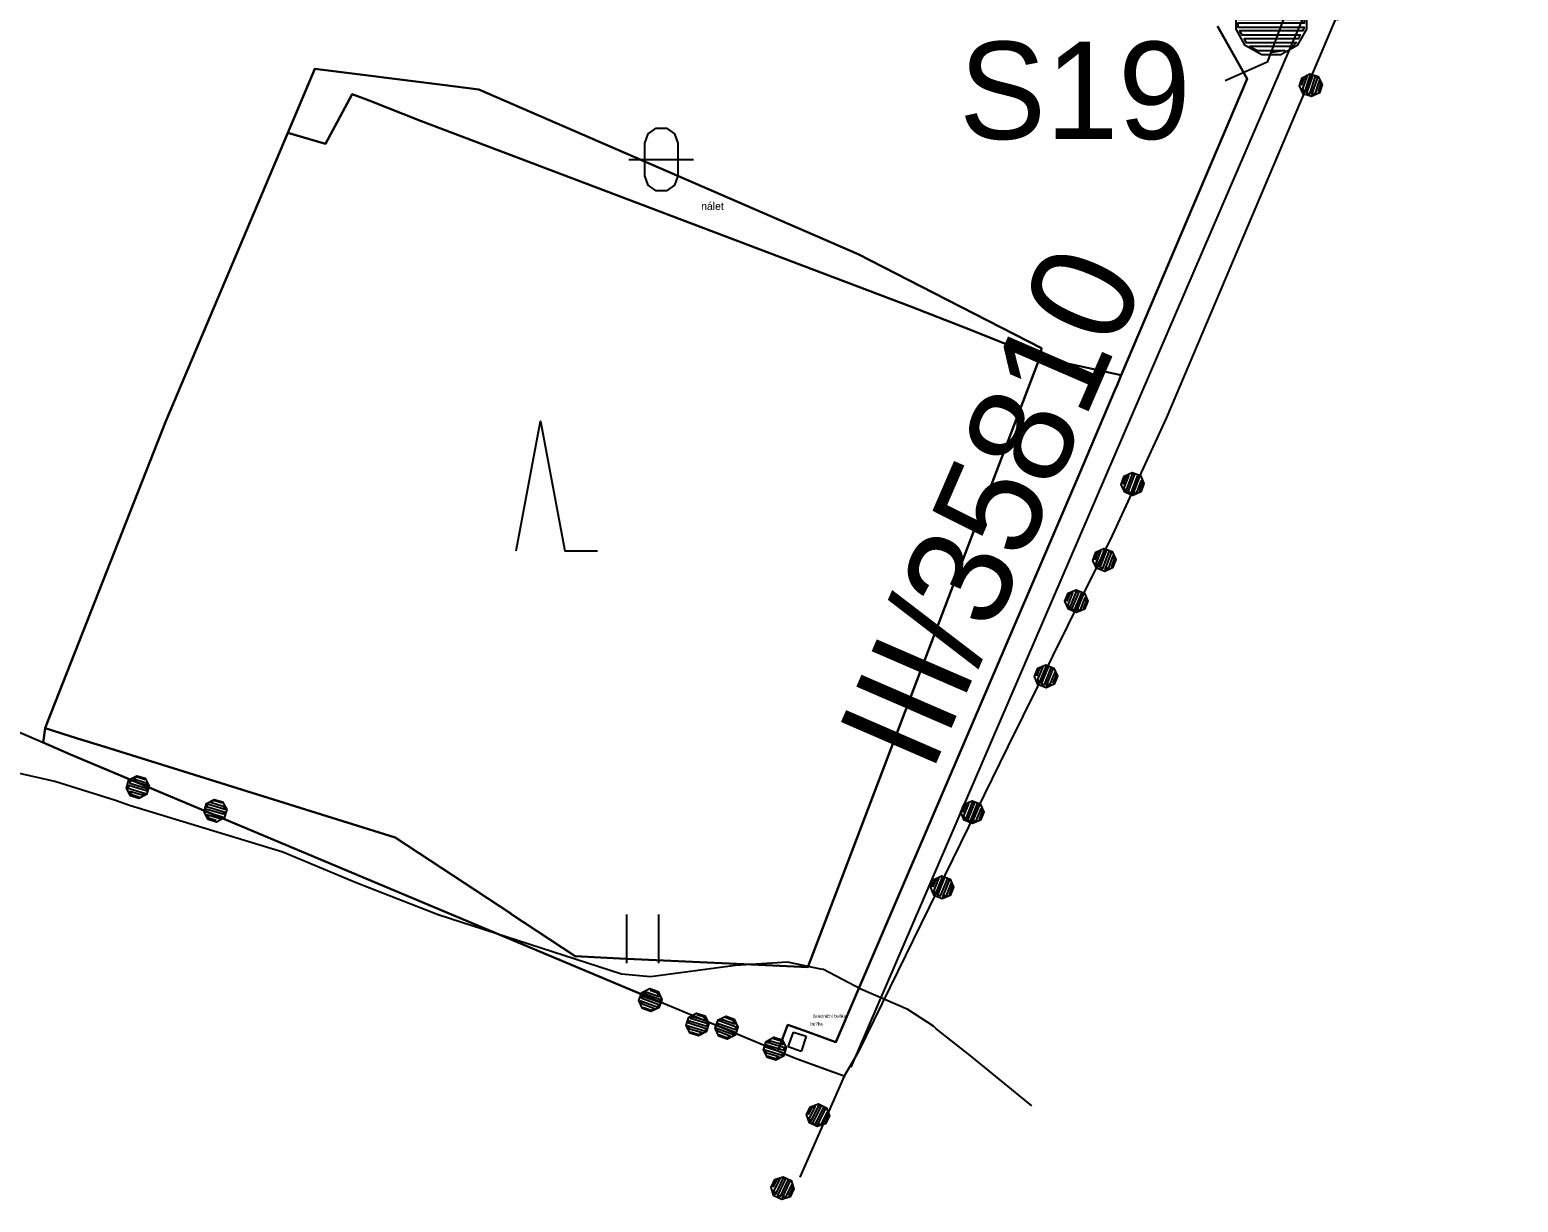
# Model space of a CAD drawing. Extents: x -645676 to -642474, y -1077513 to -1072613.
# Drawn here: x -642883 to -642653.5, y -1075517.7 to -1075337 of the extents above; entities that cross this region are included whole.
import ezdxf

# ---------------------------------------------------------------- set-up
doc = ezdxf.new("R2010")
doc.units = 0
for name, color, linetype in [('_elezni_n__tra_', 7, 'Continuous'), ('DOPRAVA', 7, 'Continuous'), ('DOPRAVA_MIMO_OBV', 7, 'Continuous'), ('Krajinn__zele____popis___stav', 7, 'Continuous'), ('KULTURY_STAV', 7, 'Continuous'), ('KULTURY_ZNACKY', 7, 'Continuous'), ('OBVOD_PU', 7, 'Continuous'), ('PC_OBJ_POPIS_NAVRH', 7, 'Continuous'), ('PC_OBJEKTY_NAVRH', 7, 'Continuous'), ('PC_STAN_NAVRH', 7, 'Continuous'), ('SDELOVACI', 7, 'Continuous'), ('SPRAV_HR_STAV', 7, 'Continuous')]:
    doc.layers.add(name, color=color, linetype=linetype)

# ---------------------------------------------------------------- blocks, each defined once
blk = doc.blocks.new('$406')
blk.add_lwpolyline([(-0.19, 0.72), (0.2, 0.72), (0.54, 0.53), (0.73, 0.19), (0.73, -0.2), (0.54, -0.54), (0.2, -0.73), (-0.19, -0.73), (-0.53, -0.54), (-0.72, -0.2), (-0.72, 0.19), (-0.53, 0.53), (-0.2, 0.72), (-0.28, 0.64), (0.28, 0.64), (0.44, 0.56), (-0.44, 0.56), (-0.52, 0.48), (0.52, 0.48), (0.56, 0.4), (-0.55, 0.4), (-0.6, 0.32), (0.6, 0.32), (0.68, 0.24), (-0.59, 0.24), (-0.65, 0.24), (-0.68, 0.16), (0.59, 0.16), (0.68, 0.16), (0.68, 0.08), (-0.59, 0.08), (-0.68, 0.08), (-0.68, 0), (0.59, 0), (0.68, 0), (0.68, -0.08), (-0.59, -0.08), (-0.68, -0.08), (-0.68, -0.16), (0.59, -0.16), (0.68, -0.16), (0.65, -0.24), (-0.62, -0.24), (-0.65, -0.24), (-0.6, -0.32), (0.6, -0.32), (0.56, -0.4), (-0.55, -0.4), (-0.52, -0.48), (0.52, -0.48), (0.44, -0.56), (-0.44, -0.56), (-0.28, -0.64), (0.28, -0.64), (-0.02, -0.69)])
blk = doc.blocks.new('3$0800')
blk.add_lwpolyline([(-0.75, 0), (0, 4), (0.75, 0), (1.75, 0)])
blk = doc.blocks.new('3$0600')
for p, q in [((-0.5, 1.5), (-0.5, 0)), ((0.5, 0), (0.5, 1.5))]:
    blk.add_line(p, q)
blk = doc.blocks.new('3$1600')
for points in [[(-0.5, 1.5), (-0.4, 1.79), (-0.15, 1.97), (0.16, 1.97), (0.41, 1.79), (0.51, 1.5), (0.51, 0.5), (0.41, 0.21), (0.16, 0.03), (-0.15, 0.03), (-0.4, 0.21), (-0.5, 0.5), (-0.5, 1.5)], [(-1, 1), (0.27, 1), (1, 1)]]:
    blk.add_lwpolyline(points)
blk = doc.blocks.new('$935')
blk.add_lwpolyline([(-2, -1), (-1, 0), (1, 0), (2, -1)])
blk = doc.blocks.new('2$0620')
for points in [[(-1.07, 0.32), (-0.88, 0.13), (-0.88, -0.14), (-1.07, -0.33), (-1.34, -0.33), (-1.53, -0.14), (-1.53, 0.13), (-1.34, 0.32), (-1.07, 0.32), (-1.08, 0.28), (-1.32, 0.28), (-1.4, 0.2), (-1, 0.2), (-0.92, 0.12), (-1.48, 0.12), (-1.48, 0.04), (-0.92, 0.04), (-0.92, -0.04), (-1.48, -0.04), (-1.48, -0.12), (-0.92, -0.12), (-1, -0.2), (-1.4, -0.2), (-1.32, -0.28), (-1.08, -0.28)], [(1.43, 0.32), (1.62, 0.13), (1.62, -0.14), (1.43, -0.33), (1.16, -0.33), (0.97, -0.14), (0.97, 0.13), (1.16, 0.32), (1.43, 0.32), (1.4, 0.28), (1.16, 0.28), (1.08, 0.2), (1.48, 0.2), (1.56, 0.12), (1, 0.12), (1, 0.04), (1.56, 0.04), (1.56, -0.04), (1, -0.04), (1, -0.12), (1.56, -0.12), (1.48, -0.2), (1.08, -0.2), (1.16, -0.28), (1.4, -0.28)]]:
    blk.add_lwpolyline(points)

msp = doc.modelspace()

# ---------------------------------------------------------------- linework, layer by layer
at = {"layer": '_elezni_n__tra_'}
for p, q in [((-642766.03, -1075493.8), (-642765.19, -1075491.51)), ((-642765.19, -1075491.51), (-642763.27, -1075492.16)), ((-642764, -1075494.5), (-642766.03, -1075493.8)), ((-642763.27, -1075492.16), (-642764, -1075494.5))]:
    msp.add_line(p, q, dxfattribs=at)
at = {"layer": 'DOPRAVA'}
msp.add_lwpolyline([(-642653.47, -1075258.11), (-642756.35, -1075496.91)], dxfattribs=at)
at = {"layer": 'DOPRAVA_MIMO_OBV'}
msp.add_lwpolyline([(-642757.41, -1075498.33), (-642764.25, -1075513.87)], dxfattribs=at)
at = {"layer": 'KULTURY_STAV'}
for points in [[(-642676.53, -1075323.31), (-642707.69, -1075396.77), (-642716.07, -1075414.98), (-642732.16, -1075447.5), (-642755.26, -1075494.63), (-642757.41, -1075498.33), (-642760.44, -1075497.22), (-642765.04, -1075495.53), (-642767.62, -1075494.46), (-642766.21, -1075490.73), (-642766.08, -1075490.39), (-642762.89, -1075491.54), (-642758.67, -1075493.07), (-642755.01, -1075484.54), (-642721.18, -1075405.56), (-642715.6, -1075392.43), (-642715.3, -1075391.8), (-642715.33, -1075391.79), (-642714.67, -1075390.24), (-642695.24, -1075344.57), (-642699.86, -1075336.44)], [(-642699.86, -1075336.44), (-642695.24, -1075344.57), (-642714.67, -1075390.24), (-642726.24, -1075387.74), (-642727.22, -1075387.53), (-642727.19, -1075387.39), (-642726.95, -1075386.07), (-642745.63, -1075376.53), (-642755.25, -1075371.61), (-642813.72, -1075346.23), (-642819.34, -1075345.51), (-642838.99, -1075343), (-642843.16, -1075352.87), (-642861.96, -1075397.33), (-642880.26, -1075443.82), (-642880.6, -1075444.68), (-642880.91, -1075446.88), (-642876.66, -1075448.7), (-642931.51, -1075425.22), (-642982.25, -1075403.81), (-643000.98, -1075395.62), (-643034.07, -1075381.69), (-643051.73, -1075373.59), (-643088.33, -1075357.65)], [(-642838.99, -1075343), (-642819.34, -1075345.51), (-642813.72, -1075346.23), (-642755.25, -1075371.61), (-642745.63, -1075376.53), (-642726.95, -1075386.07), (-642727.19, -1075387.39), (-642727.86, -1075387.14), (-642727.91, -1075387.26), (-642738.82, -1075382.9), (-642747.04, -1075379.73), (-642822.71, -1075351.06), (-642830.63, -1075347.92), (-642833.27, -1075346.93), (-642837.34, -1075354.58), (-642843.16, -1075352.87), (-642838.99, -1075343)], [(-642833.27, -1075346.93), (-642830.63, -1075347.92), (-642822.71, -1075351.06), (-642747.04, -1075379.73), (-642738.82, -1075382.9), (-642727.91, -1075387.26), (-642727.86, -1075387.14), (-642727.19, -1075387.39), (-642727.22, -1075387.53), (-642762.98, -1075481.52), (-642769.49, -1075481.21), (-642792.01, -1075480.15), (-642792.02, -1075480.15), (-642798.85, -1075479.83), (-642808.79, -1075473.26), (-642808.8, -1075473.25), (-642826.6, -1075461.5), (-642871.36, -1075447.55), (-642875.61, -1075446.23), (-642880.6, -1075444.68), (-642880.26, -1075443.82), (-642861.96, -1075397.33), (-642843.16, -1075352.87), (-642837.34, -1075354.58), (-642833.27, -1075346.93)], [(-642727.22, -1075387.53), (-642726.24, -1075387.74), (-642714.67, -1075390.24), (-642715.33, -1075391.79), (-642715.3, -1075391.8), (-642715.6, -1075392.43), (-642721.18, -1075405.56), (-642755.01, -1075484.54), (-642758.67, -1075493.07), (-642762.89, -1075491.54), (-642766.08, -1075490.39), (-642766.21, -1075490.73), (-642767.62, -1075494.46), (-642785.89, -1075486.85), (-642876.66, -1075448.7), (-642880.91, -1075446.88), (-642880.6, -1075444.68), (-642875.61, -1075446.23), (-642871.36, -1075447.55), (-642826.6, -1075461.5), (-642808.8, -1075473.25), (-642808.79, -1075473.26), (-642798.85, -1075479.83), (-642792.02, -1075480.15), (-642792.01, -1075480.15), (-642769.49, -1075481.21), (-642762.98, -1075481.52), (-642727.22, -1075387.53)]]:
    msp.add_lwpolyline(points, dxfattribs=at)
at = {"layer": 'OBVOD_PU'}
msp.add_lwpolyline([(-642676.53, -1075323.31), (-642707.69, -1075396.77), (-642716.07, -1075414.98), (-642732.16, -1075447.5), (-642755.26, -1075494.63), (-642757.41, -1075498.33), (-642765.04, -1075495.53), (-642785.89, -1075486.85), (-642876.66, -1075448.7), (-642931.51, -1075425.22), (-642982.25, -1075403.81), (-643000.98, -1075395.62), (-643034.07, -1075381.69), (-643051.73, -1075373.59), (-643088.33, -1075357.65)], dxfattribs=at)
at = {"layer": 'SDELOVACI'}
msp.add_lwpolyline([(-642728.48, -1075502.86), (-642737.73, -1075495.35), (-642743.24, -1075490.96), (-642743.61, -1075490.6), (-642747.58, -1075488.02), (-642754.81, -1075484.9), (-642760.56, -1075481.89), (-642760.99, -1075481.81), (-642766.13, -1075480.74), (-642774.14, -1075481.26), (-642787.27, -1075482.99), (-642791.75, -1075482.57), (-642819.97, -1075473.46), (-642832.61, -1075468.53), (-642843.93, -1075463.77), (-642867.57, -1075456.57), (-642869.75, -1075455.83), (-642879.11, -1075452.9), (-642899.76, -1075448.19)], dxfattribs=at)
at = {"layer": 'SPRAV_HR_STAV'}
for p, q in [((-642676.53, -1075323.31), (-642707.69, -1075396.77)), ((-642707.69, -1075396.77), (-642716.07, -1075414.98)), ((-642716.07, -1075414.98), (-642732.16, -1075447.5)), ((-642876.66, -1075448.7), (-642931.51, -1075425.22)), ((-642732.16, -1075447.5), (-642755.26, -1075494.63)), ((-642876.66, -1075448.7), (-642785.89, -1075486.85)), ((-642765.04, -1075495.53), (-642785.89, -1075486.85)), ((-642757.41, -1075498.33), (-642765.04, -1075495.53)), ((-642755.26, -1075494.63), (-642757.41, -1075498.33))]:
    msp.add_line(p, q, dxfattribs=at)

# ---------------------------------------------------------------- block references
at = {"layer": 'KULTURY_ZNACKY', "xscale": 5, "yscale": 5}
for name, p in [('3$1600', (-642785.61, -1075362)), ('3$0800', (-642804.2, -1075417.34)), ('3$0600', (-642788.47, -1075480.87))]:
    msp.add_blockref(name, p, dxfattribs=at)
at = {"layer": 'PC_OBJEKTY_NAVRH', "xscale": 5, "yscale": 5, "rotation": -110.90214800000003}
msp.add_blockref('$935', (-642690.42, -1075337.32), dxfattribs=at)
at = {"layer": 'PC_STAN_NAVRH', "xscale": 7.5, "yscale": 7.5}
msp.add_blockref('$406', (-642691.58, -1075335.38), dxfattribs=at)
at = {"layer": 'SPRAV_HR_STAV'}
for p, xscale, yscale, rotation in [((-642683.36, -1075339.42), 5, 5, -108.674282), ((-642715.01, -1075412.67), 5.000000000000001, 5.000000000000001, -110.43017300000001), ((-642723.83, -1075430.67), 5, 5, -112.07201000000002), ((-642860.53, -1075455.48), 4.999999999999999, 5.000000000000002, -16.911367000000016), ((-642739.86, -1075463.21), 5, 5, -111.85435500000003), ((-642781.2, -1075488.8), 5, 5, 160.144801), ((-642773.84, -1075492.3), 5, 5, 162.638134), ((-642764.05, -1075509.76), 4.999999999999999, 5, -115.97406899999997)]:
    msp.add_blockref('2$0620', p, dxfattribs=dict(at, xscale=xscale, yscale=yscale, rotation=rotation))

# ---------------------------------------------------------------- texts
at = {"layer": '_elezni_n__tra_'}
for s, p in [('železniční buňka', (-642762.22, -1075489.3)), ('bu?ka', (-642762.61, -1075490.5))]:
    msp.add_text(s, height=0.5, dxfattribs=at).set_placement(p)
at = {"layer": 'DOPRAVA'}
msp.add_text('III/35810', height=16, rotation=66.578, dxfattribs=at).set_placement((-642743.99, -1075451.88))
at = {"layer": 'Krajinn__zele____popis___stav'}
msp.add_text('nálet', height=1.2, dxfattribs=at).set_placement((-642779.44, -1075364.78))
at = {"layer": 'PC_OBJ_POPIS_NAVRH'}
msp.add_text('S19', height=15, dxfattribs=at).set_placement((-642739.67, -1075353.84))

doc.saveas('drawing.dxf')
